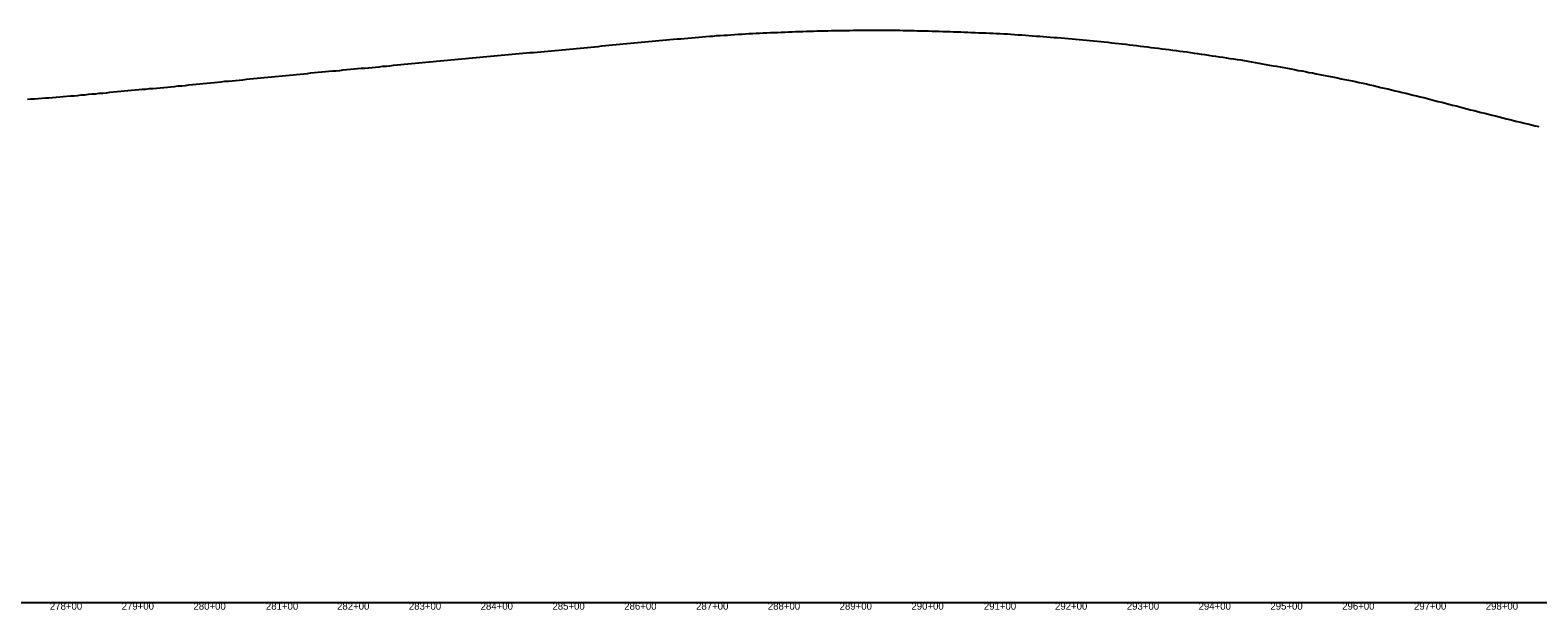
# Model space of a CAD drawing. Extents: x 69 to 2003113, y 512 to 837401.
# Drawn here: x 1906112 to 1908212, y 830494 to 831301 of the extents above; entities that cross this region are included whole.
import ezdxf

# ---------------------------------------------------------------- set-up
doc = ezdxf.new("R2010")
doc.units = 0
for name, color, linetype in [('BR_BORDER LINES', 7, 'Continuous'), ('BR_TEXT', 7, 'Continuous'), ('RD_SHT_ID', 7, 'Continuous')]:
    doc.layers.add(name, color=color, linetype=linetype)

msp = doc.modelspace()

# ---------------------------------------------------------------- linework, layer by layer
at = {"layer": 'BR_BORDER LINES'}
msp.add_line((1878363.1, 830504.3), (1926563.1, 830504.3), dxfattribs=at)
at = {"layer": 'BR_TEXT'}
for points in [[(1906863.1, 831274.7), (1906868.1, 831275.2), (1906873.1, 831275.7), (1906878.1, 831276.2), (1906883.1, 831276.7), (1906888.1, 831277.2), (1906893.1, 831277.7), (1906898.1, 831278.2), (1906903.1, 831278.7), (1906908.1, 831279.3), (1906913.1, 831279.8), (1906918.1, 831280.3), (1906923.1, 831280.7), (1906928.1, 831281.2), (1906933.1, 831281.7), (1906938.1, 831282.3), (1906943.1, 831282.7), (1906948.1, 831283.2), (1906953.1, 831283.6), (1906958.1, 831284.1), (1906963.1, 831284.6), (1906968.1, 831285.1), (1906973.1, 831285.5), (1906978.1, 831286), (1906983.1, 831286.4), (1906988.1, 831286.8), (1906993.1, 831287.3), (1906998.1, 831287.7), (1907003.1, 831288.1), (1907008.1, 831288.6), (1907013.1, 831289), (1907018.1, 831289.4), (1907023.1, 831289.8), (1907028.1, 831290.3), (1907033.1, 831290.7), (1907038.1, 831291.2), (1907043.1, 831291.6), (1907048.1, 831292), (1907053.1, 831292.5), (1907058.1, 831292.8), (1907063.1, 831293.1), (1907068.1, 831293.6), (1907073.1, 831294), (1907078.1, 831294.3), (1907083.1, 831294.5), (1907088.1, 831294.9), (1907093.1, 831295.3), (1907098.1, 831295.5), (1907103.1, 831295.8), (1907108.1, 831296.1), (1907113.1, 831296.5), (1907118.1, 831296.7), (1907123.1, 831296.9), (1907128.1, 831297.1), (1907133.1, 831297.4), (1907138.1, 831297.6), (1907143.1, 831297.8), (1907148.1, 831298), (1907153.1, 831298.2), (1907158.1, 831298.4), (1907163.1, 831298.6), (1907168.1, 831298.8), (1907173.1, 831299), (1907178.1, 831299.2), (1907183.1, 831299.4), (1907188.1, 831299.5), (1907193.1, 831299.7), (1907198.1, 831299.9), (1907203.1, 831300), (1907208.1, 831300.2), (1907213.1, 831300.4), (1907218.1, 831300.5), (1907223.1, 831300.5), (1907228.1, 831300.6), (1907233.1, 831300.8), (1907238.1, 831300.8), (1907243.1, 831300.9), (1907248.1, 831301), (1907253.1, 831301), (1907258.1, 831301.1), (1907263.1, 831301.1), (1907268.1, 831301.2), (1907273.1, 831301.2), (1907278.1, 831301.2), (1907283.1, 831301.2), (1907288.1, 831301.2), (1907293.1, 831301.2), (1907298.1, 831301.1), (1907303.1, 831301.1), (1907308.1, 831301.1), (1907313.1, 831301.1), (1907318.1, 831301.1), (1907323.1, 831301.1), (1907328.1, 831301), (1907333.1, 831300.9), (1907338.1, 831300.8), (1907343.1, 831300.6), (1907348.1, 831300.5), (1907353.1, 831300.3), (1907358.1, 831300.2), (1907363.1, 831300.1)], [(1907363.1, 831300.1), (1907368.1, 831300), (1907373.1, 831299.9), (1907378.1, 831299.7), (1907383.1, 831299.5), (1907388.1, 831299.3), (1907393.1, 831299.2), (1907398.1, 831299.1), (1907403.1, 831298.8), (1907408.1, 831298.7), (1907413.1, 831298.5), (1907418.1, 831298.3), (1907423.1, 831298.1), (1907428.1, 831297.9), (1907433.1, 831297.7), (1907438.1, 831297.6), (1907443.1, 831297.4), (1907448.1, 831297.2), (1907453.1, 831297), (1907458.1, 831296.7), (1907463.1, 831296.5), (1907468.1, 831296.2), (1907473.1, 831295.9), (1907478.1, 831295.5), (1907483.1, 831295.3), (1907488.1, 831294.9), (1907493.1, 831294.6), (1907498.1, 831294.3), (1907503.1, 831293.9), (1907508.1, 831293.5), (1907513.1, 831293.1), (1907518.1, 831292.8), (1907523.1, 831292.4), (1907528.1, 831292.1), (1907533.1, 831291.6), (1907538.1, 831291.2), (1907543.1, 831290.8), (1907548.1, 831290.4), (1907553.1, 831289.9), (1907558.1, 831289.6), (1907563.1, 831289.2), (1907568.1, 831288.7), (1907573.1, 831288.2), (1907578.1, 831287.7), (1907583.1, 831287.2), (1907588.1, 831286.7), (1907593.1, 831286.2), (1907598.1, 831285.7), (1907603.1, 831285.3), (1907608.1, 831284.8), (1907613.1, 831284.3), (1907618.1, 831283.7), (1907623.1, 831283.2), (1907628.1, 831282.6), (1907633.1, 831282.1), (1907638.1, 831281.6), (1907643.1, 831280.9), (1907648.1, 831280.3), (1907653.1, 831279.7), (1907658.1, 831279.1), (1907663.1, 831278.6), (1907668.1, 831278), (1907673.1, 831277.3), (1907678.1, 831276.6), (1907683.1, 831276), (1907688.1, 831275.4), (1907693.1, 831274.8), (1907698.1, 831274.3), (1907703.1, 831273.6), (1907708.1, 831272.9), (1907713.1, 831272.2), (1907718.1, 831271.6), (1907723.1, 831270.9), (1907728.1, 831270.2), (1907733.1, 831269.4), (1907738.1, 831268.8), (1907743.1, 831268), (1907748.1, 831267.2), (1907753.1, 831266.4), (1907758.1, 831265.7), (1907763.1, 831265), (1907768.1, 831264.3), (1907773.1, 831263.5), (1907778.1, 831262.7), (1907783.1, 831261.9), (1907788.1, 831261.2), (1907793.1, 831260.4), (1907798.1, 831259.7), (1907803.1, 831258.8), (1907808.1, 831257.9), (1907813.1, 831257), (1907818.1, 831256.2), (1907823.1, 831255.3), (1907828.1, 831254.4), (1907833.1, 831253.5), (1907838.1, 831252.7), (1907843.1, 831251.8), (1907848.1, 831250.9), (1907853.1, 831250), (1907858.1, 831249.1), (1907863.1, 831248.2)], [(1906363.1, 831228), (1906368.1, 831228.5), (1906373.1, 831229), (1906378.1, 831229.5), (1906383.1, 831230), (1906388.1, 831230.4), (1906393.1, 831230.8), (1906398.1, 831231.3), (1906403.1, 831231.8), (1906408.1, 831232.3), (1906413.1, 831232.8), (1906418.1, 831233.3), (1906423.1, 831233.8), (1906428.1, 831234.3), (1906433.1, 831234.8), (1906438.1, 831235.3), (1906443.1, 831235.8), (1906448.1, 831236.3), (1906453.1, 831236.7), (1906458.1, 831237.2), (1906463.1, 831237.6), (1906468.1, 831238.1), (1906473.1, 831238.7), (1906478.1, 831239.2), (1906483.1, 831239.6), (1906488.1, 831240.1), (1906493.1, 831240.6), (1906498.1, 831241.1), (1906503.1, 831241.6), (1906508.1, 831242.1), (1906513.1, 831242.6), (1906518.1, 831243), (1906523.1, 831243.5), (1906528.1, 831244), (1906533.1, 831244.4), (1906538.1, 831244.8), (1906543.1, 831245.3), (1906548.1, 831245.9), (1906553.1, 831246.4), (1906558.1, 831246.9), (1906563.1, 831247.3), (1906568.1, 831247.8), (1906573.1, 831248.1), (1906578.1, 831248.5), (1906583.1, 831249), (1906588.1, 831249.4), (1906593.1, 831249.9), (1906598.1, 831250.4), (1906603.1, 831250.9), (1906608.1, 831251.3), (1906613.1, 831251.8), (1906618.1, 831252.4), (1906623.1, 831252.8), (1906628.1, 831253.3), (1906633.1, 831253.8), (1906638.1, 831254.3), (1906643.1, 831254.8), (1906648.1, 831255.2), (1906653.1, 831255.7), (1906658.1, 831256.2), (1906663.1, 831256.6), (1906668.1, 831257.1), (1906673.1, 831257.6), (1906678.1, 831258), (1906683.1, 831258.5), (1906688.1, 831258.9), (1906693.1, 831259.4), (1906698.1, 831259.9), (1906703.1, 831260.3), (1906708.1, 831260.8), (1906713.1, 831261.3), (1906718.1, 831261.8), (1906723.1, 831262.3), (1906728.1, 831262.8), (1906733.1, 831263.3), (1906738.1, 831263.7), (1906743.1, 831264.1), (1906748.1, 831264.7), (1906753.1, 831265.2), (1906758.1, 831265.7), (1906763.1, 831266.1), (1906768.1, 831266.6), (1906773.1, 831267.1), (1906778.1, 831267.5), (1906783.1, 831267.9), (1906788.1, 831268.4), (1906793.1, 831268.8), (1906798.1, 831269.2), (1906803.1, 831269.6), (1906808.1, 831270), (1906813.1, 831270.3), (1906818.1, 831270.8), (1906823.1, 831271.2), (1906828.1, 831271.6), (1906833.1, 831272), (1906838.1, 831272.4), (1906843.1, 831272.9), (1906848.1, 831273.3), (1906853.1, 831273.8), (1906858.1, 831274.2), (1906863.1, 831274.7)], [(1907863.1, 831248.2), (1907868.1, 831247.2), (1907873.1, 831246.3), (1907878.1, 831245.3), (1907883.1, 831244.4), (1907888.1, 831243.5), (1907893.1, 831242.5), (1907898.1, 831241.6), (1907903.1, 831240.6), (1907908.1, 831239.5), (1907913.1, 831238.5), (1907918.1, 831237.7), (1907923.1, 831236.7), (1907928.1, 831235.8), (1907933.1, 831234.8), (1907938.1, 831233.7), (1907943.1, 831232.7), (1907948.1, 831231.6), (1907953.1, 831230.6), (1907958.1, 831229.6), (1907963.1, 831228.6), (1907968.1, 831227.5), (1907973.1, 831226.3), (1907978.1, 831225.2), (1907983.1, 831224), (1907988.1, 831222.8), (1907993.1, 831221.6), (1907998.1, 831220.5), (1908003.1, 831219.4), (1908008.1, 831218.2), (1908013.1, 831217), (1908018.1, 831215.8), (1908023.1, 831214.6), (1908028.1, 831213.4), (1908033.1, 831212.2), (1908038.1, 831210.9), (1908043.1, 831209.7), (1908048.1, 831208.5), (1908053.1, 831207.3), (1908058.1, 831206), (1908063.1, 831204.7), (1908068.1, 831203.4), (1908073.1, 831202.1), (1908078.1, 831200.8), (1908083.1, 831199.5), (1908088.1, 831198.2), (1908093.1, 831196.9), (1908098.1, 831195.7), (1908103.1, 831194.4), (1908108.1, 831193.1), (1908113.1, 831191.8), (1908118.1, 831190.5), (1908123.1, 831189.2), (1908128.1, 831188), (1908133.1, 831186.7), (1908138.1, 831185.5), (1908143.1, 831184.2), (1908148.1, 831183), (1908153.1, 831181.8), (1908158.1, 831180.5), (1908163.1, 831179.2), (1908168.1, 831178), (1908173.1, 831176.8), (1908178.1, 831175.5), (1908183.1, 831174.3), (1908188.1, 831173.2), (1908193.1, 831171.9), (1908198.1, 831170.6), (1908203.1, 831169.4), (1908208.1, 831168.1), (1908213.1, 831166.9)], [(1906108.1, 831205.2), (1906113.1, 831205.5), (1906118.1, 831205.8), (1906123.1, 831206.2), (1906128.1, 831206.5), (1906133.1, 831206.9), (1906138.1, 831207.2), (1906143.1, 831207.5), (1906148.1, 831208), (1906153.1, 831208.4), (1906158.1, 831208.8), (1906163.1, 831209.2), (1906168.1, 831209.6), (1906173.1, 831210), (1906178.1, 831210.5), (1906183.1, 831211), (1906188.1, 831211.4), (1906193.1, 831211.9), (1906198.1, 831212.4), (1906203.1, 831212.8), (1906208.1, 831213.3), (1906213.1, 831213.7), (1906218.1, 831214.2), (1906223.1, 831214.7), (1906228.1, 831215.2), (1906233.1, 831215.7), (1906238.1, 831216.2), (1906243.1, 831216.6), (1906248.1, 831217.1), (1906253.1, 831217.6), (1906258.1, 831218), (1906263.1, 831218.4), (1906268.1, 831218.9), (1906273.1, 831219.3), (1906278.1, 831219.8), (1906283.1, 831220.2), (1906288.1, 831220.6), (1906293.1, 831221.1), (1906298.1, 831221.6), (1906303.1, 831222), (1906308.1, 831222.5), (1906313.1, 831223), (1906318.1, 831223.5), (1906323.1, 831223.9), (1906328.1, 831224.4), (1906333.1, 831224.9), (1906338.1, 831225.4), (1906343.1, 831226), (1906348.1, 831226.4), (1906353.1, 831226.9), (1906358.1, 831227.4), (1906363.1, 831228)]]:
    msp.add_lwpolyline(points, dxfattribs=at)

# ---------------------------------------------------------------- texts
at = {"layer": 'RD_SHT_ID'}
for s, p in [('278+00', (1906139.4, 830494.3)), ('279+00', (1906239.4, 830494.3)), ('280+00', (1906339.4, 830494.3)), ('281+00', (1906440.3, 830494.3)), ('282+00', (1906539.4, 830494.3)), ('283+00', (1906639.4, 830494.3)), ('284+00', (1906739.4, 830494.3)), ('285+00', (1906839.4, 830494.3)), ('286+00', (1906939.4, 830494.3)), ('287+00', (1907039.4, 830494.3)), ('288+00', (1907139.4, 830494.3)), ('289+00', (1907239.4, 830494.3)), ('290+00', (1907339.4, 830494.3)), ('291+00', (1907440.3, 830494.3)), ('292+00', (1907539.4, 830494.3)), ('293+00', (1907639.4, 830494.3)), ('294+00', (1907739.4, 830494.3)), ('295+00', (1907839.4, 830494.3)), ('296+00', (1907939.4, 830494.3)), ('297+00', (1908039.4, 830494.3)), ('298+00', (1908139.4, 830494.3))]:
    msp.add_text(s, height=10, dxfattribs=at).set_placement(p)

doc.saveas('drawing.dxf')
